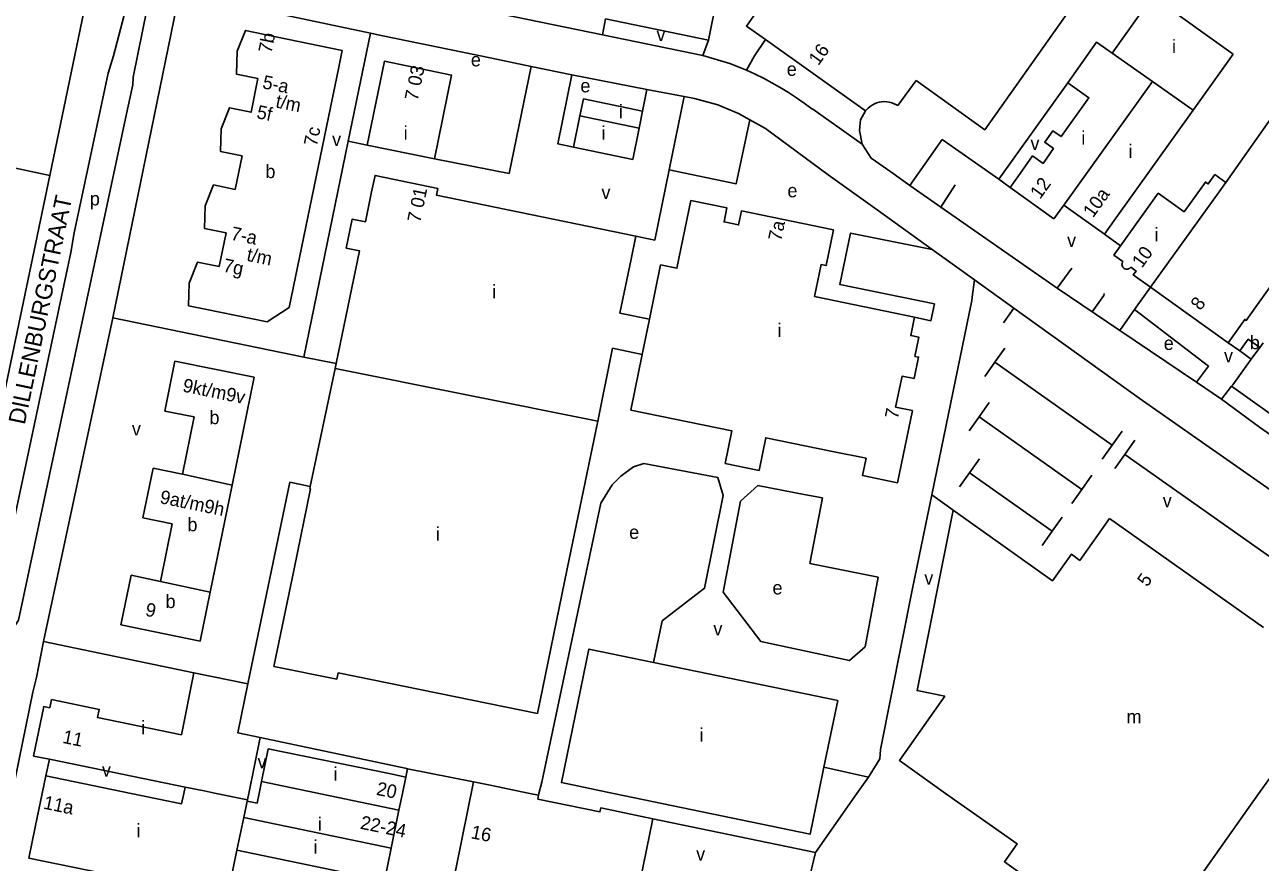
# Model space of a CAD drawing. Extents: x 157699 to 159683, y 381451 to 383293.
# Drawn here: x 158601.6 to 158968.6, y 382412.9 to 382661.5 of the extents above; entities that cross this region are included whole.
import ezdxf

# ---------------------------------------------------------------- set-up
doc = ezdxf.new("R2010")
doc.units = 0
for name, color, linetype in [('BLT_Basislijn', 7, 'Continuous'), ('BLT_Bebouwing', 7, 'Continuous'), ('BLT_Centroide', 7, 'Continuous'), ('BLT_Huisnummer', 7, 'Continuous'), ('BLT_Huisnummer_reeks', 7, 'Continuous'), ('BLT_Onderverdeling_panden', 7, 'Continuous'), ('BLT_Straatnaam', 7, 'Continuous')]:
    doc.layers.add(name, color=color, linetype=linetype)

msp = doc.modelspace()

# ---------------------------------------------------------------- linework, layer by layer
at = {"layer": 'BLT_Basislijn'}
for p, q in [((158632.1, 382668.1), (158627.93, 382652.23)), ((158633.77, 382645.88), (158637.98, 382666.43)), ((158728.37, 382667.73), (158773.15, 382658.49)), ((158774.11, 382663.19), (158773.15, 382658.49)), ((158707.5, 382658.26), (158739.86, 382651.62)), ((158773.15, 382658.49), (158802.97, 382652.34)), ((158802.97, 382652.34), (158804.66, 382656.92)), ((158821.57, 382657.09), (158818.34, 382652.23)), ((158739.86, 382651.62), (158752.05, 382649.12)), ((158815.93, 382648.04), (158818.34, 382652.23)), ((158752.05, 382649.12), (158745.49, 382617.33)), ((158752.05, 382649.12), (158764.13, 382646.65)), ((158786.4, 382642.23), (158764.13, 382646.65)), ((158911.39, 382644.28), (158890.96, 382615.6)), ((158785.12, 382635.82), (158786.4, 382642.23)), ((158797.48, 382640.13), (158786.4, 382642.23)), ((158793.01, 382618.44), (158797.48, 382640.13)), ((158813.56, 382635.17), (158816.92, 382633.29)), ((158816.92, 382633.29), (158821.64, 382630.65)), ((158835.64, 382636.37), (158850.35, 382626.01)), ((158536.17, 382632.21), (158609.02, 382616.76)), ((158821.64, 382630.65), (158840.22, 382616.97)), ((158703.32, 382625.74), (158697.69, 382626.89)), ((158864.45, 382613.81), (158874.06, 382627.42)), ((158890.96, 382615.6), (158874.06, 382627.42)), ((158723.26, 382621.65), (158745.49, 382617.33)), ((158609.02, 382616.76), (158589.07, 382521.46)), ((158840.22, 382616.97), (158854.74, 382606.55)), ((158864.45, 382613.81), (158858.83, 382617.77)), ((158894.27, 382613.18), (158890.96, 382615.6)), ((158873.65, 382607.33), (158864.45, 382613.81)), ((158877.98, 382613.93), (158873.65, 382607.33)), ((158871.16, 382594.77), (158854.74, 382606.55)), ((158927.1, 382595.86), (158922.27, 382599.31)), ((158883.71, 382585.76), (158871.16, 382594.77)), ((158883.71, 382585.77), (158874.54, 382592.34)), ((158895.41, 382577.37), (158883.71, 382585.77)), ((158908.27, 382583.25), (158926.81, 382570.76)), ((158935.96, 382583.55), (158931.2, 382576.91)), ((158892.35, 382573.03), (158895.41, 382577.37)), ((158932.64, 382550.68), (158895.41, 382577.37)), ((158931.2, 382576.91), (158926.81, 382570.76)), ((158926.81, 382570.76), (158949.58, 382555.4)), ((158962.51, 382564.65), (158958.99, 382567.09)), ((158969.39, 382567.03), (158968.39, 382565.68)), ((158889.71, 382561.3), (158892.67, 382565.48)), ((158684.48, 382562.78), (158694.11, 382560.9)), ((158886.76, 382557.11), (158889.71, 382561.3)), ((158924.59, 382536.67), (158889.71, 382561.3)), ((158949.58, 382555.4), (158957.06, 382550.35)), ((158980.45, 382539.61), (158960.07, 382554.19)), ((158885.04, 382545.14), (158888, 382549.33)), ((158882.08, 382540.96), (158885.04, 382545.14)), ((158915.58, 382523.58), (158885.04, 382545.14)), ((158924.59, 382536.67), (158927.54, 382540.86)), ((158928.33, 382533.94), (158931.28, 382538.13)), ((158921.63, 382532.49), (158924.59, 382536.67)), ((158925.37, 382529.76), (158928.33, 382533.94)), ((158974.65, 382501.24), (158928.33, 382533.94)), ((158782.41, 382530.23), (158778.64, 382527.49)), ((158785.48, 382531.29), (158782.41, 382530.23)), ((158807.44, 382527.05), (158785.48, 382531.29)), ((158882.21, 382528.48), (158885.16, 382532.66)), ((158778.64, 382527.49), (158776.05, 382524.92)), ((158879.25, 382524.29), (158882.21, 382528.48)), ((158906.78, 382511.13), (158882.21, 382528.48)), ((158915.58, 382523.58), (158918.53, 382527.77)), ((158667.88, 382465.88), (158680.36, 382525.66)), ((158680.36, 382525.66), (158686.41, 382524.41)), ((158776.05, 382524.92), (158772.7, 382519.49)), ((158833.55, 382521.99), (158819.29, 382524.75)), ((158912.62, 382519.4), (158915.58, 382523.58)), ((158838.5, 382521.04), (158833.55, 382521.99)), ((158838.5, 382521.04), (158834.81, 382501.59)), ((158877.4, 382517.43), (158871.01, 382521.97)), ((158906.78, 382511.13), (158909.74, 382515.31)), ((158903.83, 382506.94), (158906.78, 382511.13)), ((158855.11, 382497.51), (158834.81, 382501.59)), ((158605.05, 382467.78), (158607.18, 382478.38)), ((158607.18, 382478.38), (158651.85, 382469.15)), ((158605.05, 382467.78), (158604.02, 382463.33)), ((158608.96, 382443.46), (158607.82, 382438.54)), ((158714.77, 382438.19), (158715.26, 382440.66)), ((158715.26, 382440.66), (158734.86, 382436.77)), ((158838.98, 382441.07), (158852.18, 382438.15)), ((158788.16, 382425.83), (158836.48, 382415.8)), ((158834.2, 382406.33), (158836.48, 382415.8))]:
    msp.add_line(p, q, dxfattribs=at)
for points in [[(158609.02, 382616.76), (158619.67, 382667.64), (158619.98, 382671.21), (158619.82, 382672.73), (158617.29, 382675.37)], [(158627.78, 382574.46), (158646.65, 382666.74), (158651.26, 382669.61)], [(158651.26, 382669.61), (158655.48, 382669.36), (158704.29, 382658.95)], [(158704.29, 382658.95), (158701.92, 382647.47), (158697.69, 382626.89)], [(158704.29, 382658.95), (158707.5, 382658.26)], [(158627.93, 382652.23), (158626.35, 382647.12), (158616.3, 382599.72), (158615.3, 382593.85), (158592.52, 382487), (158592.73, 382483.96), (158593.85, 382482.78), (158595.1, 382482.02), (158597.16, 382482.16), (158598.35, 382482.54), (158599.78, 382484.77), (158632.13, 382636.44)], [(158815.93, 382648.04), (158811.02, 382649.96), (158802.97, 382652.34)], [(158815.93, 382648.04), (158818.5, 382646.85), (158821.03, 382645.59), (158823.53, 382644.25), (158825.99, 382642.85), (158828.41, 382641.37), (158830.79, 382639.83), (158833.12, 382638.22), (158835.41, 382636.55), (158835.64, 382636.37)], [(158632.13, 382636.44), (158633.67, 382643.62), (158633.77, 382645.88)], [(158764.13, 382646.65), (158759.9, 382626.14), (158764.57, 382625.17)], [(158797.48, 382640.13), (158800.56, 382639.56), (158807.41, 382637.72), (158813.56, 382635.17)], [(158793.01, 382618.44), (158812.85, 382614.21), (158816.92, 382633.29)], [(158851.3, 382635.89), (158849.79, 382633.25), (158849.53, 382630.1), (158850.35, 382626.01)], [(158697.69, 382626.89), (158684.48, 382562.78)], [(158858.83, 382617.77), (158852.97, 382621.89), (158850.35, 382626.01)], [(158783.08, 382598.72), (158788.7, 382597.56), (158793.01, 382618.44)], [(158873.65, 382607.33), (158908.27, 382583.25)], [(158865.86, 382574.71), (158870.75, 382573.61), (158871.77, 382578.61), (158843.73, 382584.33), (158846.84, 382599.59), (158871.16, 382594.77)], [(158908.27, 382583.25), (158912.62, 382589.19)], [(158882.86, 382579.66), (158882.99, 382580.66), (158883.71, 382585.77)], [(158922.21, 382581.66), (158922.12, 382581.14), (158918.68, 382576.23)], [(158871.01, 382521.97), (158882.86, 382579.66)], [(158607.18, 382478.38), (158627.78, 382574.46)], [(158627.78, 382574.46), (158684.48, 382562.78)], [(158949.58, 382555.4), (158953.18, 382560.1), (158931.2, 382576.91)], [(158960.07, 382554.19), (158960.38, 382554.57), (158965.91, 382562.22)], [(158957.06, 382550.35), (158960.07, 382554.19)], [(158984.3, 382514.32), (158978.4, 382518.63), (158932.64, 382550.68)], [(159007.23, 382514.92), (158968.3, 382542.05), (158957.06, 382550.35)], [(158790.9, 382484.6), (158803.52, 382494.22), (158809, 382521.71), (158807.44, 382527.05)], [(158819.29, 382524.75), (158814.21, 382520.06), (158809, 382493.07), (158820.24, 382478.37)], [(158772.7, 382519.49), (158755.17, 382436.65)], [(158865.3, 382494.17), (158871.01, 382521.97)], [(158855.11, 382497.51), (158851.2, 382476.85)], [(158855.6, 382443.55), (158855.74, 382446.35), (158865.3, 382494.17)], [(158790.9, 382484.6), (158788.31, 382472.21)], [(158851.2, 382476.85), (158846.55, 382472.77), (158820.24, 382478.37)], [(158583.87, 382342.43), (158582.82, 382342.64), (158580.69, 382344.1), (158580.25, 382344.99), (158580.69, 382351.18), (158592.27, 382405.81), (158597.9, 382433.33), (158604.02, 382463.33)], [(158671.54, 382449.93), (158714.62, 382440.79), (158715.26, 382440.66)], [(158852.18, 382438.15), (158852.73, 382438.91), (158855.6, 382443.55)], [(158755.17, 382436.65), (158754.33, 382433.33), (158754.2, 382432.81)], [(158836.48, 382415.8), (158848.72, 382433.33), (158852.18, 382438.15)]]:
    msp.add_lwpolyline(points, dxfattribs=at)
at = {"layer": 'BLT_Bebouwing'}
for p, q in [((158804.66, 382656.92), (158774.11, 382663.19)), ((158851.3, 382635.89), (158821.57, 382657.09)), ((158866.32, 382644.97), (158860.87, 382637.49)), ((158766.49, 382634.42), (158764.57, 382625.17)), ((158785.12, 382635.82), (158784.08, 382630.77)), ((158723.26, 382621.65), (158703.32, 382625.74)), ((158894.27, 382613.18), (158907.3, 382603.89)), ((158907.3, 382603.89), (158910.2, 382607.95)), ((158910.2, 382607.95), (158922.27, 382599.31)), ((158790.47, 382590.19), (158787.16, 382574.08)), ((158935.96, 382583.55), (158958.99, 382567.09)), ((158865.86, 382574.71), (158836.15, 382580.79)), ((158787.16, 382574.08), (158785.01, 382563.63)), ((158785.01, 382563.63), (158781.6, 382547.07)), ((158962.51, 382564.65), (158965.91, 382562.22)), ((158965.91, 382562.22), (158968.39, 382565.68)), ((158646.21, 382561.63), (158643.16, 382546.81)), ((158646.21, 382561.63), (158669.75, 382556.84)), ((158669.75, 382556.84), (158663.16, 382524.79)), ((158643.16, 382546.81), (158651.91, 382545.09)), ((158651.91, 382545.09), (158648.41, 382528.09)), ((158639.7, 382529.89), (158636.66, 382515.1)), ((158639.7, 382529.89), (158648.41, 382528.09)), ((158663.16, 382524.79), (158656.64, 382493.06)), ((158686.49, 382523.74), (158681.59, 382499.99)), ((158686.41, 382524.41), (158686.28, 382523.78)), ((158686.28, 382523.78), (158686.49, 382523.74)), ((158636.66, 382515.1), (158645.42, 382513.36)), ((158645.42, 382513.36), (158641.9, 382496.26)), ((158923.83, 382514.91), (158914.99, 382502.47)), ((158633.19, 382498.15), (158641.9, 382496.26)), ((158681.59, 382499.99), (158675.6, 382471.02)), ((158656.64, 382493.06), (158653.66, 382478.55)), ((158630.14, 382483.34), (158653.66, 382478.55)), ((158667.88, 382465.88), (158651.85, 382469.15)), ((158675.6, 382471.02), (158694.31, 382467.19)), ((158694.31, 382467.19), (158694.71, 382469.14)), ((158694.71, 382469.14), (158753.93, 382457.02)), ((158968.06, 382433.23), (158979.04, 382448.6)), ((158608.96, 382443.46), (158649.19, 382435.22)), ((158838.98, 382441.07), (158837.38, 382433.33)), ((158667.75, 382431.42), (158667.68, 382431.07)), ((158710.41, 382417.04), (158712.74, 382428.37)), ((158708.42, 382407.41), (158710.41, 382417.04))]:
    msp.add_line(p, q, dxfattribs=at)
for points in [[(158813.46, 382699.81), (158805.67, 382661.82), (158804.66, 382656.92)], [(158866.32, 382644.97), (158886.74, 382630.33), (158928.69, 382689.69)], [(158821.57, 382657.09), (158815.94, 382661.1), (158818.99, 382665.41), (158822.5, 382670.34)], [(158936.51, 382669.95), (158924.53, 382653.05)], [(158960.51, 382652.79), (158936.51, 382669.95)], [(158650.26, 382578.07), (158650.41, 382584.81), (158652.95, 382591.05), (158659.34, 382589.73), (158661.38, 382599.68), (158654.99, 382600.99), (158655.14, 382607.76), (158657.66, 382613.94), (158664.06, 382612.6), (158666.12, 382622.56), (158659.71, 382623.88), (158659.93, 382630.62), (158662.41, 382636.85), (158668.81, 382635.52), (158670.84, 382645.49), (158664.44, 382646.81), (158664.65, 382653.59), (158667.14, 382659.77), (158676.18, 382657.89), (158695.86, 382653.83), (158694.85, 382648.93), (158680.15, 382577.58), (158673.56, 382573.28)], [(158924.53, 382653.05), (158919.93, 382656.32), (158911.39, 382644.28)], [(158948.61, 382636.14), (158960.51, 382652.79)], [(158703.32, 382625.74), (158708.43, 382650.64), (158728.37, 382646.54), (158723.26, 382621.65)], [(158911.39, 382644.28), (158917.66, 382639.8), (158909.41, 382628.27), (158906.98, 382630.01), (158904.53, 382626.59), (158907.16, 382624.71), (158904.06, 382620.33), (158900.95, 382622.53), (158897.22, 382617.32), (158894.27, 382613.18)], [(158976.73, 382640.78), (158958.31, 382614.68)], [(158766.49, 382634.42), (158767.53, 382639.47), (158785.12, 382635.82)], [(158860.87, 382637.49), (158860.5, 382637.71), (158859.83, 382638.05), (158859.12, 382638.31), (158858.38, 382638.5), (158857.64, 382638.61), (158856.88, 382638.65), (158856.12, 382638.6), (158855.38, 382638.47), (158854.65, 382638.27), (158853.94, 382637.99), (158853.27, 382637.63), (158852.65, 382637.21), (158852.06, 382636.72), (158851.3, 382635.89)], [(158922.27, 382599.31), (158925.18, 382603.38), (158948.61, 382636.14)], [(158958.99, 382567.09), (158963.95, 382574.02), (158964.38, 382573.71), (158967.29, 382577.78), (158999.92, 382623.41), (159007.36, 382633.57), (159013.9, 382628.87)], [(158764.57, 382625.17), (158782.16, 382621.52), (158784.08, 382630.77)], [(158694.11, 382560.9), (158701.02, 382594.36), (158697.09, 382595.17), (158698.85, 382603.8), (158702.8, 382602.99), (158704.62, 382611.86), (158705.63, 382616.75), (158724.24, 382612.91), (158723.84, 382610.94), (158783.08, 382598.72)], [(158958.31, 382614.68), (158955.12, 382616.99), (158953.11, 382614.21), (158952.28, 382614.8), (158945.96, 382605.96), (158938.26, 382611.47), (158927.1, 382595.86)], [(158799.45, 382609.29), (158795.31, 382589.18), (158790.47, 382590.19)], [(158841.77, 382600.62), (158814.46, 382606.21), (158813.61, 382602.05), (158809.32, 382602.93), (158810.17, 382607.09), (158799.45, 382609.29)], [(158836.15, 382580.79), (158838.13, 382590.31), (158839.6, 382590.01), (158841.77, 382600.62)], [(158783.08, 382598.72), (158781.68, 382591.92), (158778.37, 382575.89), (158787.16, 382574.08)], [(158927.1, 382595.86), (158925.12, 382593.1), (158927.77, 382591.19), (158927.63, 382590.97), (158927.5, 382590.58), (158927.48, 382590.3), (158927.52, 382590.02), (158927.61, 382589.75), (158927.75, 382589.51), (158927.93, 382589.31), (158928.14, 382589.14), (158928.37, 382589.03), (158928.5, 382588.98), (158928.63, 382588.95), (158928.77, 382588.93), (158928.91, 382588.92), (158929.05, 382588.93), (158929.2, 382588.95), (158929.34, 382588.98), (158929.47, 382589.03), (158929.6, 382589.09), (158929.72, 382589.16), (158929.84, 382589.24), (158929.94, 382589.32), (158930.03, 382589.42), (158930.11, 382589.52), (158931.7, 382588.38), (158930.86, 382587.2), (158935.96, 382583.55)], [(158673.56, 382573.28), (158668.75, 382574.28), (158655.16, 382577.08), (158650.26, 382578.07)], [(158841.55, 382534.84), (158851.48, 382532.82), (158850.45, 382527.64), (158860.86, 382525.56), (158865.25, 382546.98), (158860.26, 382548.01), (158862.18, 382557.17), (158865.76, 382556.44), (158867.06, 382562.84), (158866.01, 382563.05), (158867.17, 382568.73), (158864.74, 382569.22), (158865.86, 382574.71)], [(158968.39, 382565.68), (158964.99, 382568.12), (158962.51, 382564.65)], [(158771.76, 382543.84), (158776.2, 382565.45), (158785.01, 382563.63)], [(158686.41, 382524.41), (158693.81, 382559.49)], [(158693.81, 382559.49), (158694.11, 382560.9)], [(158781.6, 382547.07), (158811.63, 382540.94), (158809.65, 382531.25), (158819.72, 382529.19), (158821.7, 382538.89), (158841.55, 382534.84)], [(158753.93, 382457.02), (158762.71, 382500.01), (158771.76, 382543.84)], [(158877.4, 382517.43), (158866.62, 382463.85), (158874.88, 382462.18)], [(158914.99, 382502.47), (158912.48, 382504.3), (158906.87, 382496.47), (158877.4, 382517.43)], [(158969.49, 382482.53), (158923.83, 382514.91)], [(158633.19, 382498.15), (158630.32, 382484.3), (158630.14, 382483.34)], [(158837.38, 382433.33), (158834.88, 382421.25), (158776.43, 382433.33), (158760.97, 382436.53), (158769.18, 382476.16), (158788.31, 382472.21)], [(158788.31, 382472.21), (158843.09, 382460.89), (158838.98, 382441.07)], [(158651.85, 382469.15), (158648.1, 382450.76), (158623.23, 382455.84), (158623.73, 382458.28), (158609.51, 382461.19)], [(158671.54, 382449.93), (158664.9, 382451.29), (158667.88, 382465.88)], [(158609.51, 382461.19), (158609.01, 382458.76), (158607.24, 382459.12), (158604.23, 382444.43), (158608.96, 382443.46)], [(158874.88, 382462.18), (158861.4, 382443.14), (158875.11, 382433.33), (158896.35, 382418.39), (158892.59, 382413.03), (158903.43, 382405.33), (158901.23, 382402.76)], [(158671.54, 382449.93), (158668.15, 382433.33), (158667.75, 382431.42)], [(158671.94, 382436.87), (158673.93, 382446.55), (158709.87, 382439.19), (158714.77, 382438.19)], [(158607.82, 382438.54), (158606.76, 382433.33), (158604.7, 382423.28)], [(158649.19, 382435.22), (158648.81, 382433.33), (158648.18, 382430.28), (158633.24, 382433.33), (158607.82, 382438.54)], [(158667.68, 382431.07), (158670.63, 382430.46), (158671.22, 382433.33), (158671.94, 382436.87)], [(158712.74, 382428.37), (158713.77, 382433.33), (158714.77, 382438.19)], [(158727.91, 382402.53), (158734.86, 382436.77)], [(158734.86, 382436.77), (158739.82, 382435.76), (158751.65, 382433.33), (158754.2, 382432.81)], [(158754.2, 382432.81), (158753.96, 382431.63), (158772.45, 382427.84), (158772.69, 382429), (158788.16, 382425.83)], [(158940.58, 382394.4), (158968.06, 382433.23)], [(158788.16, 382425.83), (158784.39, 382407.35)], [(158604.7, 382423.28), (158602.83, 382414.12), (158641.48, 382406.21)]]:
    msp.add_lwpolyline(points, dxfattribs=at)
at = {"layer": 'BLT_Onderverdeling_panden'}
for p, q in [((158936.57, 382644.6), (158924.53, 382653.05)), ((158936.57, 382644.6), (158910.2, 382607.95)), ((158948.61, 382636.14), (158936.57, 382644.6)), ((158784.08, 382630.77), (158766.49, 382634.42)), ((158649.19, 382435.22), (158654.85, 382434.06)), ((158671.94, 382436.87), (158712.74, 382428.37)), ((158666.68, 382426.15), (158667.68, 382431.07)), ((158666.68, 382426.15), (158664.6, 382416.49)), ((158710.41, 382417.04), (158666.68, 382426.15)), ((158664.6, 382416.49), (158662.61, 382406.8)), ((158664.6, 382416.49), (158708.42, 382407.41))]:
    msp.add_line(p, q, dxfattribs=at)
for points in [[(158958.31, 382614.68), (158956.34, 382611.89), (158935.96, 382583.55)], [(158693.81, 382559.49), (158771.76, 382543.84)], [(158648.41, 382528.09), (158663.16, 382524.79)], [(158641.9, 382496.26), (158656.64, 382493.06)], [(158654.85, 382434.06), (158658.42, 382433.33), (158667.75, 382431.42)]]:
    msp.add_lwpolyline(points, dxfattribs=at)

# ---------------------------------------------------------------- texts
at = {"layer": 'BLT_Centroide'}
for s, p in [('v', (158789.23, 382656.64)), ('i', (158942.34, 382653.06)), ('e', (158734.1, 382649.12)), ('e', (158827.93, 382646.31)), ('e', (158766.63, 382641.4)), ('i', (158778.08, 382633.72)), ('i', (158714.14, 382627.41)), ('i', (158772.93, 382627.41)), ('i', (158915.42, 382625.92)), ('v', (158692.89, 382625.5)), ('v', (158900.31, 382624.29)), ('i', (158929.41, 382621.95)), ('b', (158673.06, 382615.95)), ('p', (158620.91, 382607.85)), ('v', (158772.89, 382609.74)), ('e', (158828.12, 382610.26)), ('i', (158937.18, 382597.23)), ('v', (158911.19, 382595.55)), ('i', (158740.42, 382580.28)), ('i', (158825.2, 382568.81)), ('e', (158939.91, 382564.95)), ('b', (158965.45, 382565.16)), ('v', (158957.79, 382561.29)), ('b', (158656.45, 382542.91)), ('v', (158633.41, 382539.56)), ('v', (158939.6, 382518.28)), ('b', (158649.91, 382511.14)), ('i', (158723.69, 382508.36)), ('e', (158781.12, 382508.86)), ('v', (158868.78, 382495.3)), ('e', (158823.68, 382492.39)), ('b', (158643.42, 382488.34)), ('v', (158806.14, 382480.2)), ('m', (158928.86, 382454.12)), ('i', (158636.2, 382450.88)), ('i', (158802.03, 382448.72)), ('v', (158670.73, 382440.81)), ('v', (158624.52, 382438.34)), ('i', (158693.27, 382437.12)), ('i', (158634.78, 382420.31)), ('i', (158688.68, 382422.25)), ('i', (158687.35, 382415.48)), ('v', (158801.02, 382413.4))]:
    msp.add_text(s, height=4, dxfattribs=at).set_placement(p)
at = {"layer": 'BLT_Huisnummer'}
for s, rotation, p in [('16', 54.5119, (158837.33, 382649.16)), ('7 03', 78.3665, (158718.29, 382638.71)), ('12', 54.2287, (158903.14, 382609.48)), ('7 01', 78.3454, (158719.07, 382602.53)), ('10a', 54.4289, (158918.87, 382603.95)), ('10', 54.2287, (158933.41, 382589.04)), ('8', 54.5311, (158950.82, 382576.43)), ('5', 54.543, (158934.97, 382494.39)), ('11', 348.4307, (158612.6, 382448.35)), ('20', 348.4298, (158705.81, 382432.93)), ('11a', 348.4306, (158606.92, 382428.83))]:
    msp.add_text(s, height=4, rotation=rotation, dxfattribs=at).set_placement(p)
at = {"layer": 'BLT_Huisnummer_reeks'}
for s, rotation, p in [('7b', 78.3687, (158674.84, 382652.82)), ('5-a', 348.3772, (158671.98, 382642.65)), ('t/m', 348.3772, (158675.9, 382636.98)), ('5f', 348.2499, (158670.25, 382633.78)), ('7c', 78.3615, (158688.33, 382625.21)), ('7-a', 348.4127, (158662.58, 382597.72)), ('7a', 78.4751, (158826.26, 382597.06)), ('t/m', 348.2281, (158667.3, 382591.47)), ('7g', 348.3367, (158660.29, 382588.25)), ('9kt/m9v', 348.4313, (158648.27, 382552.64)), ('7', 78.4743, (158860.92, 382544.26)), ('9at/m9h', 348.4313, (158641.5, 382519.5)), ('9', 348.4277, (158637.18, 382486.1)), ('22-24', 348.4139, (158701.03, 382422.88)), ('16', 348.702, (158733.9, 382420.05))]:
    msp.add_text(s, height=4, rotation=rotation, dxfattribs=at).set_placement(p)
at = {"layer": 'BLT_Straatnaam'}
msp.add_text('DILLENBURGSTRAAT', height=5, rotation=78.2074, dxfattribs=at).set_placement((158601.58, 382542.58))

doc.saveas('drawing.dxf')
